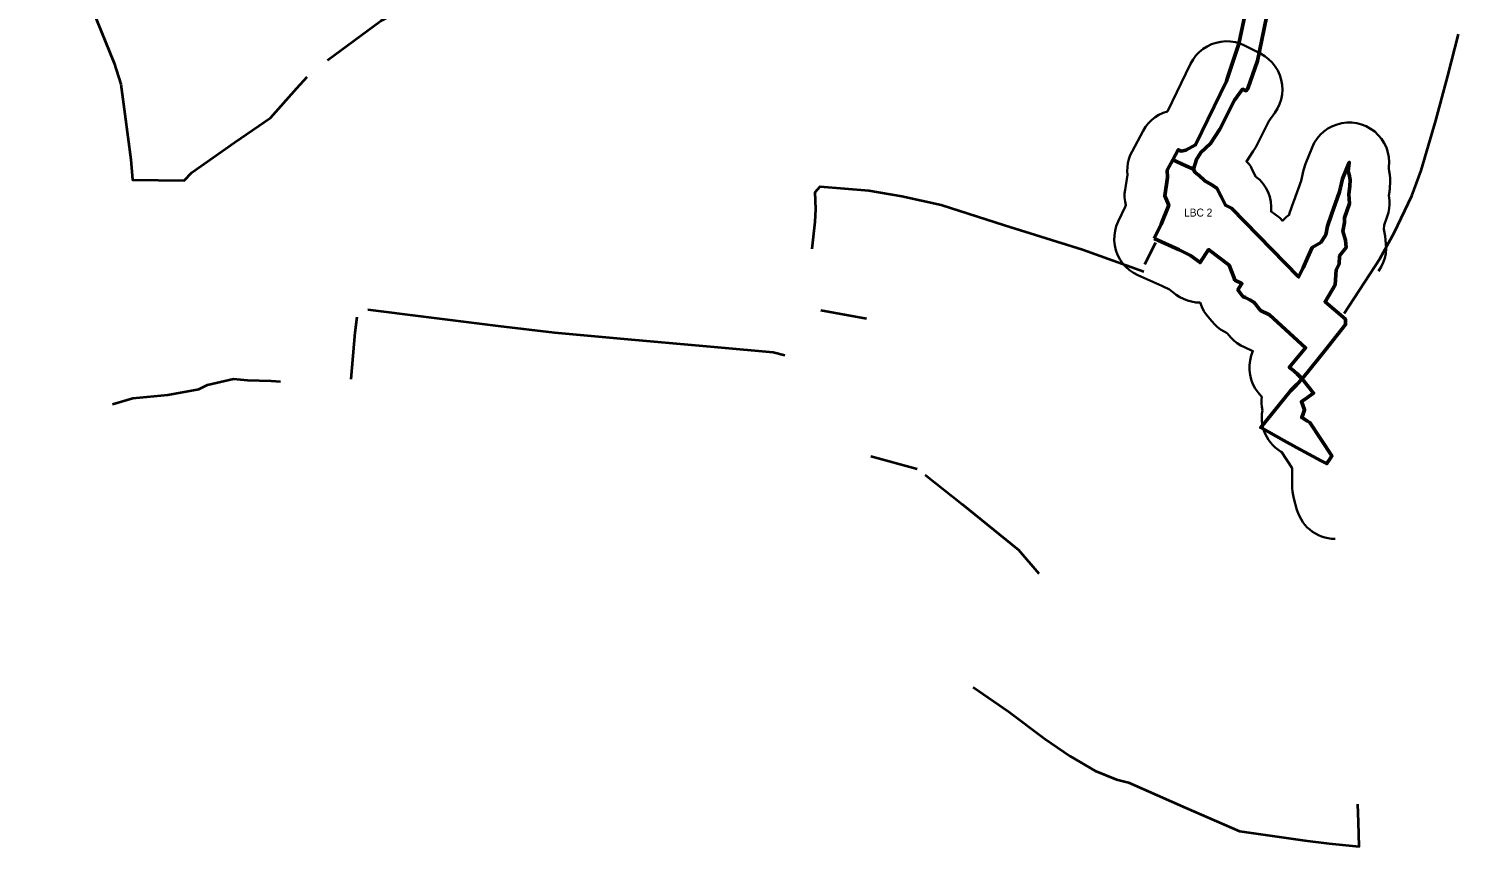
# Model space of a CAD drawing. Extents: x -555426 to -553015, y -1186745 to -1182687.
# Drawn here: x -555096 to -553310, y -1184736 to -1183714 of the extents above; entities that cross this region are included whole.
import ezdxf
from ezdxf.enums import TextEntityAlignment as Align

# ---------------------------------------------------------------- set-up
doc = ezdxf.new("R2010")
doc.units = 0
doc.header["$LTSCALE"] = 4
for name, color, linetype, lineweight in [('12', 7, 'Continuous', 53), ('14', 7, 'Continuous', 53), ('51', 7, 'Continuous', 40), ('7', 7, 'Continuous', 35)]:
    doc.layers.add(name, color=color, linetype=linetype, lineweight=lineweight)
doc.layers.add('13', color=7, linetype='Continuous')

msp = doc.modelspace()

# ---------------------------------------------------------------- linework, layer by layer
at = {"layer": '12'}
for points in [[(-553570.03, -1183665.12), (-553583.88, -1183732.87), (-553598.72, -1183776.49), (-553599.33, -1183779.63), (-553638.05, -1183859.17), (-553650.17, -1183865.76), (-553655.99, -1183866.78), (-553659.67, -1183865.22), (-553666.309, -1183877.637)], [(-553640.65, -1183889.28), (-553636.95, -1183877.35), (-553631.4, -1183868.6), (-553619.44, -1183857.32), (-553607.57, -1183839.44), (-553589.46, -1183803.27), (-553579.54, -1183789.62), (-553574.74, -1183791.55), (-553572.63, -1183788.46), (-553560.8, -1183754.18), (-553549.47, -1183699.63)]]:
    msp.add_lwpolyline(points, dxfattribs=at)
at = {"layer": '14'}
for points in [[(-553504.87, -1184151.41), (-553484.09, -1184125.63), (-553472.51, -1184111.2), (-553450.55, -1184083.82), (-553450.78, -1184076.89), (-553476.304, -1184055.306), (-553463.69, -1184034.17), (-553462.34, -1184015.28), (-553458.74, -1184008.31), (-553458.15, -1183997.82), (-553449.96, -1183987.59), (-553450.88, -1183978.18), (-553451.96, -1183974.23), (-553453.98, -1183966.85), (-553452.1, -1183956.16), (-553452.04, -1183950.11), (-553445.82, -1183932.28), (-553446.73, -1183920.6), (-553445.24, -1183910.57), (-553444.85, -1183902.91), (-553446.37, -1183896.02), (-553447.47, -1183892.13), (-553446.14, -1183881.07), (-553454.56, -1183901.72), (-553458.14, -1183917.89), (-553468.31, -1183946.22), (-553473.1, -1183960.53), (-553475.4, -1183971.52), (-553481.72, -1183980.97), (-553492.27, -1183987.37), (-553498.05, -1184000.33), (-553503.5, -1184012.68), (-553509.429, -1184024.111), (-553593.32, -1183938.23), (-553600.54, -1183934.49), (-553606.03, -1183923.81), (-553611.55, -1183913.18), (-553618.67, -1183908.59), (-553626.65, -1183904.05), (-553634, -1183897.09), (-553634.67, -1183896.58), (-553638.87, -1183893.41), (-553640.65, -1183889.28), (-553650.19, -1183885.2), (-553666.309, -1183877.637), (-553673.4, -1183890.9), (-553673.2, -1183899.7), (-553676.66, -1183922.68), (-553671.53, -1183934.39), (-553681.07, -1183958.12), (-553689.7, -1183976.31)], [(-553689.7, -1183976.31), (-553658.74, -1183990.2), (-553644.53, -1183997.23), (-553632.37, -1184006.24), (-553621.85, -1183989.98), (-553596.03, -1184009.58), (-553590.07, -1184024.62), (-553589.07, -1184028.06), (-553580.1, -1184032.43), (-553585.19, -1184040.49), (-553578.84, -1184048.47), (-553576.02, -1184049.98), (-553570.37, -1184053), (-553564.72, -1184056.02), (-553556.93, -1184066.34), (-553545.55, -1184071.44), (-553500.71, -1184112.76), (-553520.93, -1184137.34), (-553517.9, -1184139.66), (-553511.28, -1184145.17), (-553504.87, -1184151.41), (-553511.7, -1184158.61), (-553515.54, -1184162.66), (-553519.34, -1184166.39), (-553556.677, -1184212.497), (-553527.84, -1184228.51), (-553512.1, -1184237.25), (-553481.05, -1184254.16), (-553474.48, -1184257.57), (-553473.65, -1184256.43), (-553472.72, -1184255.42), (-553471.17, -1184253.05), (-553467.8, -1184248), (-553495.13, -1184206.36), (-553498.14, -1184204.48), (-553505.38, -1184199.98), (-553503.8, -1184195.45), (-553501.83, -1184190.23), (-553505.83, -1184180.04), (-553501.18, -1184176.88), (-553496.76, -1184173.61), (-553490.69, -1184169.42), (-553504.87, -1184151.41)]]:
    msp.add_lwpolyline(points, dxfattribs=at)
at = {"layer": '51'}
for p, q in [((-553701.354, -1184008.317), (-553687.724, -1183981.289)), ((-554106.147, -1184065.85), (-554049.362, -1184076.116)), ((-554043.857, -1184248.148), (-553985.839, -1184263.917))]:
    msp.add_line(p, q, dxfattribs=at)
for points in [[(-555096.259, -1183500.696), (-555050.637, -1183609.844), (-555016.334, -1183690.35), (-554989.423, -1183757.11), (-554981.106, -1183783.327), (-554976.024, -1183820.635), (-554968.516, -1183877.229), (-554966.438, -1183902.87), (-554901.757, -1183903.794), (-554892.286, -1183893.629), (-554839.155, -1183856.09), (-554793.88, -1183825.366), (-554760.962, -1183788.058), (-554748.083, -1183774.083)], [(-554722.904, -1183753.292), (-554656.144, -1183703.857), (-554636.97, -1183694.155), (-554490.514, -1183641.718), (-554303.17, -1183572.417), (-554231.271, -1183546.197)], [(-553452.274, -1184069.761), (-553407.69, -1184001.384), (-553389.729, -1183968.928), (-553368.015, -1183922.612), (-553356.004, -1183891.195), (-553337.755, -1183828.706), (-553322.739, -1183772.802), (-553309.668, -1183720.52)], [(-554117.276, -1183988.913), (-554113.349, -1183955.417), (-554112.541, -1183939.363), (-554113.465, -1183918.11), (-554107.229, -1183911.18), (-554046.475, -1183916.147), (-554005.241, -1183923.075), (-553956.153, -1183934.164), (-553877.034, -1183959.574), (-553779.204, -1183989.72), (-553702.671, -1184017.2)], [(-554693.206, -1184151.895), (-554688.143, -1184093.792), (-554685.833, -1184074.157)], [(-554672.442, -1184064.785), (-554602.776, -1184073.475), (-554509.647, -1184085.152), (-554439.112, -1184093.571), (-554347.287, -1184101.853), (-554234.895, -1184111.901), (-554165.808, -1184118.418), (-554151.421, -1184122.165)], [(-554991.278, -1184183.076), (-554965.868, -1184175.915), (-554922.324, -1184171.757), (-554883.4, -1184164.364), (-554872.543, -1184158.936), (-554840.318, -1184151.774), (-554822.647, -1184153.044), (-554792.963, -1184153.968), (-554781.297, -1184155.008)], [(-553975.782, -1184271.482), (-553929.532, -1184308.155), (-553859.537, -1184365.213), (-553834.126, -1184394.981)], [(-553915.961, -1184536.965), (-553871.955, -1184567.226), (-553826.562, -1184601.646), (-553794.799, -1184623.245), (-553763.383, -1184641.725), (-553737.049, -1184652.352), (-553722.034, -1184656.395), (-553650.307, -1184688.041), (-553583.084, -1184717.146), (-553501.541, -1184728.811), (-553471.048, -1184732.621), (-553433.741, -1184736.086), (-553434.665, -1184705.823), (-553435.473, -1184683.3)]]:
    msp.add_lwpolyline(points, dxfattribs=at)
at = {"layer": '7'}
for points in [[(-553722.567, -1183881.813), (-553721.376, -1183876.819), (-553719.679, -1183871.972), (-553717.493, -1183867.326), (-553703.763, -1183841.646), (-553700.792, -1183836.747), (-553697.267, -1183832.229), (-553693.239, -1183828.155), (-553688.762, -1183824.579), (-553683.897, -1183821.552), (-553678.712, -1183819.114), (-553673.277, -1183817.3), (-553644.286, -1183757.746), (-553641.29, -1183752.44), (-553637.671, -1183747.538), (-553633.483, -1183743.112), (-553628.787, -1183739.229), (-553623.654, -1183735.946), (-553618.159, -1183733.312), (-553612.385, -1183731.365), (-553606.418, -1183730.135), (-553600.344, -1183729.641), (-553594.256, -1183729.889), (-553588.243, -1183730.875), (-553582.395, -1183732.586), (-553576.798, -1183734.995), (-553557.008, -1183744.985), (-553551.673, -1183748.106), (-553546.764, -1183751.862), (-553542.356, -1183756.194), (-553538.515, -1183761.037), (-553535.302, -1183766.318), (-553532.765, -1183771.954), (-553530.943, -1183777.86), (-553529.863, -1183783.946), (-553529.542, -1183790.119), (-553529.986, -1183796.284), (-553531.187, -1183802.347), (-553533.126, -1183808.215), (-553535.775, -1183813.8), (-553539.093, -1183819.015), (-553546.593, -1183829.336), (-553562.861, -1183861.826), (-553565.914, -1183867.095), (-553574.577, -1183879.712), (-553571.659, -1183882.853), (-553569.178, -1183886.348), (-553567.176, -1183890.138), (-553562.613, -1183898.925), (-553557.938, -1183902.995), (-553553.815, -1183907.622), (-553550.31, -1183912.734), (-553547.48, -1183918.249), (-553545.37, -1183924.076), (-553544.014, -1183930.124), (-553543.433, -1183936.295), (-553543.637, -1183942.49), (-553534.634, -1183949.273), (-553532.551, -1183950.928), (-553529.384, -1183954.043), (-553524.409, -1183949.068), (-553521.058, -1183946.667), (-553520.514, -1183944.66), (-553515.724, -1183930.349), (-553515.37, -1183929.327), (-553506.272, -1183903.984), (-553503.378, -1183890.912), (-553500.859, -1183882.842), (-553492.439, -1183862.192), (-553489.725, -1183856.569), (-553486.332, -1183851.328), (-553482.311, -1183846.55), (-553477.727, -1183842.311), (-553472.65, -1183838.677), (-553467.159, -1183835.703), (-553461.341, -1183833.437), (-553455.285, -1183831.914), (-553449.087, -1183831.157), (-553442.843, -1183831.179), (-553436.651, -1183831.979), (-553430.606, -1183833.545), (-553424.804, -1183835.851), (-553419.335, -1183838.863), (-553414.283, -1183842.533), (-553409.728, -1183846.804), (-553405.741, -1183851.609), (-553402.385, -1183856.874), (-553399.71, -1183862.516), (-553397.76, -1183868.448), (-553396.564, -1183874.576), (-553396.141, -1183880.806), (-553396.498, -1183887.04), (-553396.727, -1183888.95), (-553396.024, -1183892.139), (-553395.258, -1183896.538), (-553394.887, -1183900.988), (-553394.915, -1183905.453), (-553395.305, -1183913.113), (-553395.781, -1183917.906), (-553396.423, -1183922.238), (-553395.955, -1183928.615)], [(-553738.985, -1183984.737), (-553739.645, -1183978.653), (-553739.557, -1183972.535), (-553738.722, -1183966.472), (-553737.154, -1183960.557), (-553734.874, -1183954.878), (-553726.244, -1183936.688), (-553725.072, -1183934.455), (-553726.229, -1183929.736), (-553726.791, -1183924.91), (-553726.749, -1183920.052), (-553726.103, -1183915.236), (-553723.285, -1183896.523), (-553723.387, -1183892.037), (-553723.24, -1183886.904), (-553722.567, -1183881.813)], [(-553395.955, -1183928.615), (-553395.841, -1183933.724), (-553396.249, -1183938.818), (-553397.176, -1183943.844), (-553398.61, -1183948.75), (-553402.366, -1183959.517), (-553402.733, -1183964.691), (-553401.117, -1183973.315), (-553400.197, -1183982.725), (-553399.97, -1183988.743), (-553400.473, -1183994.744), (-553401.699, -1184000.64), (-553403.63, -1184006.344), (-553406.237, -1184011.773), (-553409.482, -1184016.846)], [(-553555.399, -1184173.521), (-553555.928, -1184173.064), (-553560.01, -1184168.555), (-553563.509, -1184163.58), (-553566.373, -1184158.214), (-553568.559, -1184152.538), (-553570.035, -1184146.638), (-553570.777, -1184140.601), (-553570.775, -1184134.519), (-553570.029, -1184128.482), (-553568.551, -1184122.582), (-553566.361, -1184116.908), (-553577.108, -1184112.149), (-553581.637, -1184109.863), (-553585.911, -1184107.129), (-553589.885, -1184103.976), (-553593.52, -1184100.436), (-553596.778, -1184096.547), (-553598, -1184094.926), (-553599.607, -1184094.068), (-553602.443, -1184092.549), (-553606.799, -1184089.923), (-553610.865, -1184086.868), (-553614.6, -1184083.417), (-553617.964, -1184079.604), (-553624.315, -1184071.624), (-553627.678, -1184066.867), (-553630.404, -1184061.717), (-553632.448, -1184056.261), (-553637.738, -1184055.964), (-553642.968, -1184055.11), (-553648.079, -1184053.71), (-553653.013, -1184051.778), (-553657.717, -1184049.337), (-553662.137, -1184046.414), (-553670.706, -1184040.065), (-553680.067, -1184035.434), (-553710.167, -1184021.93), (-553715.586, -1184019.088), (-553720.618, -1184015.605), (-553725.187, -1184011.534), (-553729.224, -1184006.935), (-553732.669, -1184001.877), (-553735.47, -1183996.437), (-553737.586, -1183990.695), (-553738.985, -1183984.737)], [(-553463.773, -1184351.761), (-553468.031, -1184351.534), (-553472.279, -1184350.939), (-553476.46, -1184349.983), (-553480.543, -1184348.671), (-553484.499, -1184347.015), (-553488.299, -1184345.025), (-553491.914, -1184342.717), (-553495.318, -1184340.108), (-553498.486, -1184337.217), (-553501.394, -1184334.064), (-553504.022, -1184330.674), (-553506.349, -1184327.072), (-553508.359, -1184323.283), (-553510.037, -1184319.336), (-553511.37, -1184315.259), (-553515.36, -1184301.019), (-553516.343, -1184296.826), (-553516.96, -1184292.563), (-553517.209, -1184288.264), (-553517.576, -1184263.275), (-553530.89, -1184242.989), (-553531.771, -1184242.442), (-553535.289, -1184240.041), (-553538.59, -1184237.351), (-553541.65, -1184234.389), (-553544.447, -1184231.177), (-553546.96, -1184227.739), (-553549.172, -1184224.099), (-553551.065, -1184220.285), (-553552.628, -1184216.323), (-553553.847, -1184212.242), (-553554.715, -1184208.073), (-553555.225, -1184203.845), (-553555.373, -1184199.589), (-553555.158, -1184195.335), (-553554.582, -1184191.115), (-553555.369, -1184186.769), (-553555.77, -1184182.369), (-553555.781, -1184177.952), (-553555.399, -1184173.521)]]:
    msp.add_lwpolyline(points, dxfattribs=at)

# ---------------------------------------------------------------- texts
at = {"layer": '13', "width": 0.95}
msp.add_text('LBC 2', height=10, dxfattribs=at).set_placement((-553634.818, -1183948.737), align=Align.CENTER)

doc.saveas('drawing.dxf')
